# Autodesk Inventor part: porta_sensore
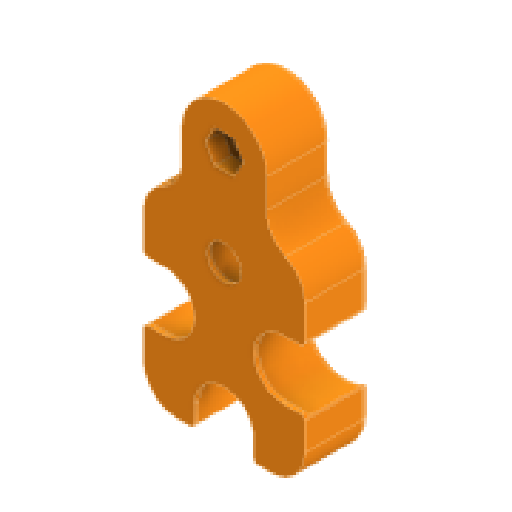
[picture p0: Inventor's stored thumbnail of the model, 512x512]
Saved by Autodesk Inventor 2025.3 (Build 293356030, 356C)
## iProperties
Created: 2025-09
Part Number: porta_sensore
Material: Plastica PET
Document SubType Name: Modeling
Designer: Ryzen5700u
Density: 1.541 g/cm^3
Appearance: Arancione
Mass: 32.5454 g
Surface Area: 78.2138 cm^2
Volume: 21.1196 cm^3
Author: Ryzen5700u
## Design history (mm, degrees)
sketch "Schizzo1"
  geometry: L1 (-10, -96)-(-10, 38) reference; L2 (9, -97)-(-9, -97) reference; L3 (10, 38)-(10, -96) reference; L4 (10, -97)-(-10, -97); L5 (-10, -97)-(-10, -77); L6 (-10, -77)-(10, -77); L7 (10, -77)-(10, -97); L8 (-10, 38)-(10, 38) reference; C1 r 2.25 at (0, -87) reference; A1 r 1 centre (-9, -96) between (-10, -96) and (-9, -97) reference; A2 r 1 centre (9, -96) between (9, -97) and (10, -96) reference; 7 further points
  constraints: 8 end point, 2 parallel, 1 horizontal, 1 perpendicular
  dimensions: "d0" = 20 distance of L5.end L6.end; "d1" = 20 distance of L4.end L5.end
extrude "Estrusione1" new body sketch "Schizzo1" distance "d2" = 40; taper "d3" = 0 deg
sketch "Schizzo2"
  geometry: L1 (1, 40)-(19, 40) reference; L2 (20, 40)-(0, 40); L3 (0, 40)-(0, 25); L4 (0, 25)-(20, 25); L5 (20, 25)-(20, 40); 5 further points
  constraints: 8 end point, 2 parallel, 1 horizontal, 1 perpendicular
  dimensions: "d4" = 20 distance of L4.end L3.end; "d5" = 15 distance of L3.end L2.end
extrude "Estrusione2" join sketch "Schizzo2" distance "d6" = 15; taper "d7" = 0 deg
sketch "Schizzo3"
  geometry: L1 (0, -15)-(20, -15) reference; L2 (10, -15)-(10, -78.397); L3 (20, -15)-(46.316, -15); L4 (0, -15)-(-26.316, -15); L5 (29, -15)-(-9, -15); L6 (-9, -15)-(-9, -60); L7 (-9, -60)-(29, -60); L8 (29, -60)-(29, -15); L9 (-9, -37.5)-(29, -37.5); L10 (-4, -28.5)-(-9, -28.5); L11 (24, -28.5)-(29, -28.5); L12 (-4, -46.5)-(-9, -46.5); L13 (1, -55)-(1, -60); L14 (19, -55)-(19, -60); L15 (24, -46.5)-(29, -46.5); C1 r 5.5 at (10, -22.614); A1 r 9 centre (-4, -37.5) between (-4, -28.5) and (-4, -46.5); A2 r 9 centre (24, -37.5) between (24, -28.5) and (24, -46.5); A3 r 9 centre (10, -55) between (1, -55) and (19, -55); 9 further points
  constraints: 28 end point, 13 point on line, 6 perpendicular, 6 point on circle, 4 centre point, 4 tangent, 3 midpoint, 2 horizontal, 2 parallel, 1 symmetric about line, 1 vertical, 1 other
  dimensions: "d28" = 45 distance of L6.end L5.end; "d29" = 38 distance of L6.end L7.end; "d30" = 18 diameter of A1; "d31" = 18 diameter of A2; "d32" = 5 distance from line of L6 A1.centre; "d33" = 5 distance from line of L8 A2.centre; "d34" = 11 diameter of C1; "d35" = 18 diameter of A3; "d36" = 5 distance from line of L7 A3.centre
extrude "Estrusione3" join sketch "Schizzo3" distance "d16" = 15; taper "d17" = 0 deg
sketch "Schizzo4"
  geometry: L1 (10, -77)-(-10, -77) reference; 2 further points
  dimensions: "d18" = 10 distance from line of L1 point (0, -87)
hole "Foro1" sketch "Schizzo4" at (0, -87) diameter "d19" = 4.5; stored, may be unused: countersink angle "d23" = 90 deg, drill point angle "d25" = 118 deg; dims "d20" = 6, "d21" = 8, "d22" = 20, "d24" = 8
sketch "Schizzo5"
  geometry: L1 (-10, -77)-(-10, -96) reference; L2 (-10, -112)-(-19, -112) reference; L3 (-19, -112)-(-19, -127.017) reference; L4 (-19, -141.983)-(-19, -157) reference; L5 (-19, -157)-(-7.483, -157) reference; L6 (7.483, -157)-(19, -157) reference; L7 (19, -157)-(19, -141.983) reference; L8 (19, -127.017)-(19, -112) reference; L9 (19, -112)-(10, -112) reference; L10 (10, -97)-(10, -112) reference; L11 (-14, -141.5)-(-19, -141.5); L12 (-19, -141.5)-(-19, -143.5); L13 (-14, -127.5)-(-19, -127.5); L14 (-19, -127.5)-(-19, -125.5); L15 (14, -127.5)-(19, -127.5); L16 (19, -127.5)-(19, -125.5); L17 (14, -141.5)-(19, -141.5); L18 (19, -143.5)-(19, -141.5); L19 (7, -152)-(7, -157); L20 (7, -157)-(9, -157); L21 (-7, -152)-(-7, -157); L22 (-7, -157)-(-9, -157); L23 (-9, -97)-(-10, -97) reference; L24 (-10, -97)-(-10, -112) reference; L25 (10, -97)-(9, -97) reference; L26 (10, -96)-(10, -77) reference; L27 (10, -77)-(-10, -77) reference; C1 r 5.5 at (0, -119.614) reference; C2 r 4 at (0, -119.614); A1 r 9 centre (-14, -134.5) between (-19, -141.983) and (-19, -127.017) reference; A2 r 9 centre (0, -152) between (7.483, -157) and (-7.483, -157) reference; A3 r 9 centre (14, -134.5) between (19, -127.017) and (19, -141.983) reference; A4 r 7 centre (0, -152) between (7, -152) and (-7, -152); A5 r 7 centre (-14, -134.5) between (-14, -141.5) and (-14, -127.5); A6 r 7 centre (14, -134.5) between (14, -127.5) and (14, -141.5); A7 r 1 centre (-9, -96) between (-10, -96) and (-9, -97) reference; A8 r 1 centre (9, -96) between (9, -97) and (10, -96) reference; 8 further points
  constraints: 24 end point, 8 point on line, 7 perpendicular, 6 point on circle, 4 centre point, 4 coincident, 4 tangent, 1 horizontal, 1 parallel
  dimensions: "d37" = 14 diameter of A4; "d38" = 14 diameter of A5; "d39" = 14 diameter of A6; "d40" = 8 diameter of C2
extrude "Estrusione4" join sketch "Schizzo5" distance "d41" = 1; taper "d42" = 0 deg
fillet "Raccordo3" dims "d43" = 8
fillet "Raccordo4" dims "d47" = 1
sketch "Schizzo6"
  geometry: L1 (4.4, -87)-(2.2, -90.811); L2 (2.2, -90.811)-(-2.2, -90.811); L3 (-2.2, -90.811)-(-4.4, -87); L4 (-4.4, -87)-(-2.2, -83.189); L5 (-2.2, -83.189)-(2.2, -83.189); L6 (2.2, -83.189)-(4.4, -87); C1 r 2.25 at (0, -87) reference; 2 further points
  constraints: 12 end point, 13 other
  dimensions: "d51" = 4.4 distance of L1.end L2.end
extrude "Estrusione5" cut sketch "Schizzo6" distance "d48" = 20; taper "d49" = 0 deg
fillet "Raccordo5" dims "d52" = 2
fillet "Raccordo6" dims "d53" = 5
sketch "Schizzo8"
  geometry: L1 (-10, -96)-(-10, -77) reference; L2 (9, -97)-(-9, -97) reference; L3 (10, -77)-(10, -96) reference; L4 (-10, -77)-(10, -77) reference; L5 (-10, -97)-(-10, -104) reference; L6 (10, -77)-(-10, -77); L7 (-10, -77)-(-10, -97); L8 (-10, -97)-(10, -97); L9 (10, -97)-(10, -77); C1 r 2.25 at (0, -87) reference; A1 r 1 centre (-9, -96) between (-10, -96) and (-9, -97) reference; A2 r 1 centre (9, -96) between (9, -97) and (10, -96) reference; 1 further point
  constraints: 8 end point, 2 parallel, 1 horizontal, 1 perpendicular
extrude "Estrusione7" cut sketch "Schizzo8" extent not by distance; stored distance "d58" = 0; taper "d59" = 0 deg
sketch "Schizzo9"
  geometry: L1 (20, -40)-(0, -40) reference; L2 (20, -25)-(20, -40) reference; L3 (0, -25)-(20, -25) reference; L4 (0, -40)-(0, -25) reference; 1 further point
extrude "Estrusione8" join sketch "Schizzo9" distance "d60" = 10; taper "d61" = 0 deg
sketch "Schizzo10"
  geometry: L1 (-10, 65)-(10, 65) reference; L2 (19, 25.5)-(19, 33.613) reference; L3 (10, 65)-(10, 48) reference; L4 (-10, 65)-(10, 65) reference; L5 (-10, 65)-(-10, 48) reference; L6 (-19, 33.613)-(-19, 25.5) reference; L7 (-19, 9.5)-(-19, 3) reference; L8 (-11, -5)-(-8, -5) reference; L9 (8, -5)-(11, -5) reference; L10 (19, 3)-(19, 9.5) reference; C1 r 10 at (0, 55); C2 r 5.5 at (0, 32.386) reference; A1 r 1 centre (18, 9.5) between (19, 9.5) and (18.894, 9.947) reference; A2 r 9 centre (14, 17.5) between (18.894, 25.053) and (18.894, 9.947) reference; A3 r 1 centre (18, 25.5) between (18.894, 25.053) and (19, 25.5) reference; A4 r 8 centre (11, 33.613) between (19, 33.613) and (14.5, 40.806) reference; A5 r 8 centre (18, 48) between (10, 48) and (14.5, 40.806) reference; A6 r 8 centre (-18, 48) between (-14.5, 40.806) and (-10, 48) reference; A7 r 8 centre (-11, 33.613) between (-14.5, 40.806) and (-19, 33.613) reference; A8 r 1 centre (-18, 25.5) between (-19, 25.5) and (-18.894, 25.053) reference; A9 r 9 centre (-14, 17.5) between (-18.894, 9.947) and (-18.894, 25.053) reference; A10 r 1 centre (-18, 9.5) between (-18.894, 9.947) and (-19, 9.5) reference; A11 r 8 centre (-11, 3) between (-19, 3) and (-11, -5) reference; A12 r 1 centre (-8, -4) between (-8, -5) and (-7.553, -4.894) reference; A13 r 9 centre (0, 0) between (7.553, -4.894) and (-7.553, -4.894) reference; A14 r 1 centre (8, -4) between (7.553, -4.894) and (8, -5) reference; A15 r 8 centre (11, 3) between (11, -5) and (19, 3) reference; 6 further points
  constraints: 1 centre point, 1 tangent
  dimensions: "d62" = 20 diameter of C1
extrude "Estrusione9" cut sketch "Schizzo10" extent not by distance; stored distance "d63" = 0; taper "d64" = 0 deg
sketch "Schizzo11"
  geometry: A1 r 10 centre (0, -97) between (10, -97) and (-10, -97) reference; 1 further point
hole "Foro2" sketch "Schizzo11" at (0, -97) diameter "d65" = 4.5; stored, may be unused: countersink angle "d69" = 90 deg, drill point angle "d71" = 118 deg; dims "d66" = 6, "d67" = 8, "d68" = 4.6, "d70" = 8
sketch "Schizzo12"
  geometry: L1 (4.5, -97)-(2.25, -100.897); L2 (2.25, -100.897)-(-2.25, -100.897); L3 (-2.25, -100.897)-(-4.5, -97); L4 (-4.5, -97)-(-2.25, -93.103); L5 (-2.25, -93.103)-(2.25, -93.103); L6 (2.25, -93.103)-(4.5, -97); C1 r 2.25 at (0, -97) reference; 2 further points
  constraints: 12 end point, 1 coincident, 13 other
  dimensions: "d72" = 4.5 distance of L1.end L2.end
extrude "Estrusione10" cut sketch "Schizzo12" distance "d73" = 4; taper "d74" = 0 deg
fillet "Raccordo9" dims "d75" = 1
sketch "Schizzo13"
  geometry: C1 r 2.25 at (0, 55) reference; C2 r 0.5 at (0, 15); 2 further points
  constraints: 1 centre point, 1 coincident
  dimensions: "d76" = 40 distance of point (0, 15) C1.centre; "d77" = 1 diameter of C2
extrude "Estrusione11" cut sketch "Schizzo13" distance "d78" = 0.1; taper "d79" = 0 deg
node "Solido1"
node "Riferimento1"
node "Linea chiusa proiettata1"
node "Linea chiusa proiettata2"
node "Linea chiusa proiettata3"
node "Linea chiusa proiettata4"
